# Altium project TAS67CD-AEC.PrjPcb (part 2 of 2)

## Sheet PROC191_TAS1.SchDoc
size 431 x 279 mm; Date: Not shown in title block; ApprovedBy: Not shown in title block; CheckedBy: Not shown in title block; Author: Not shown in title block; CompanyName: Not shown in title block; Engineer: Not shown in title block; Organization: Not shown in title block; Address1: Not shown in title block; Address2: Not shown in title block; Address3: Not shown in title block; Address4: Not shown in title block; DocumentNumber: 4; Revision: Use project parameter SCH_Rev; SheetNumber: 5; SheetTotal: 6; PageSetup: Record=PageOptions¦CenterHorizontal=True¦CenterVertical=True¦PrintScale=1.00¦XCorrection=1.00¦YCorrection=1.00¦PrintKind=0¦BorderSize=5000000¦LeftOffset=0¦BottomOffset=0¦Orientation=2¦PaperLength=1000¦PaperWidth=1000¦Scale=100¦PaperSource=15¦PrintQuality=600¦MediaType=1¦DitherType=10¦PaperKind=Letter¦PrintScaleMode=1
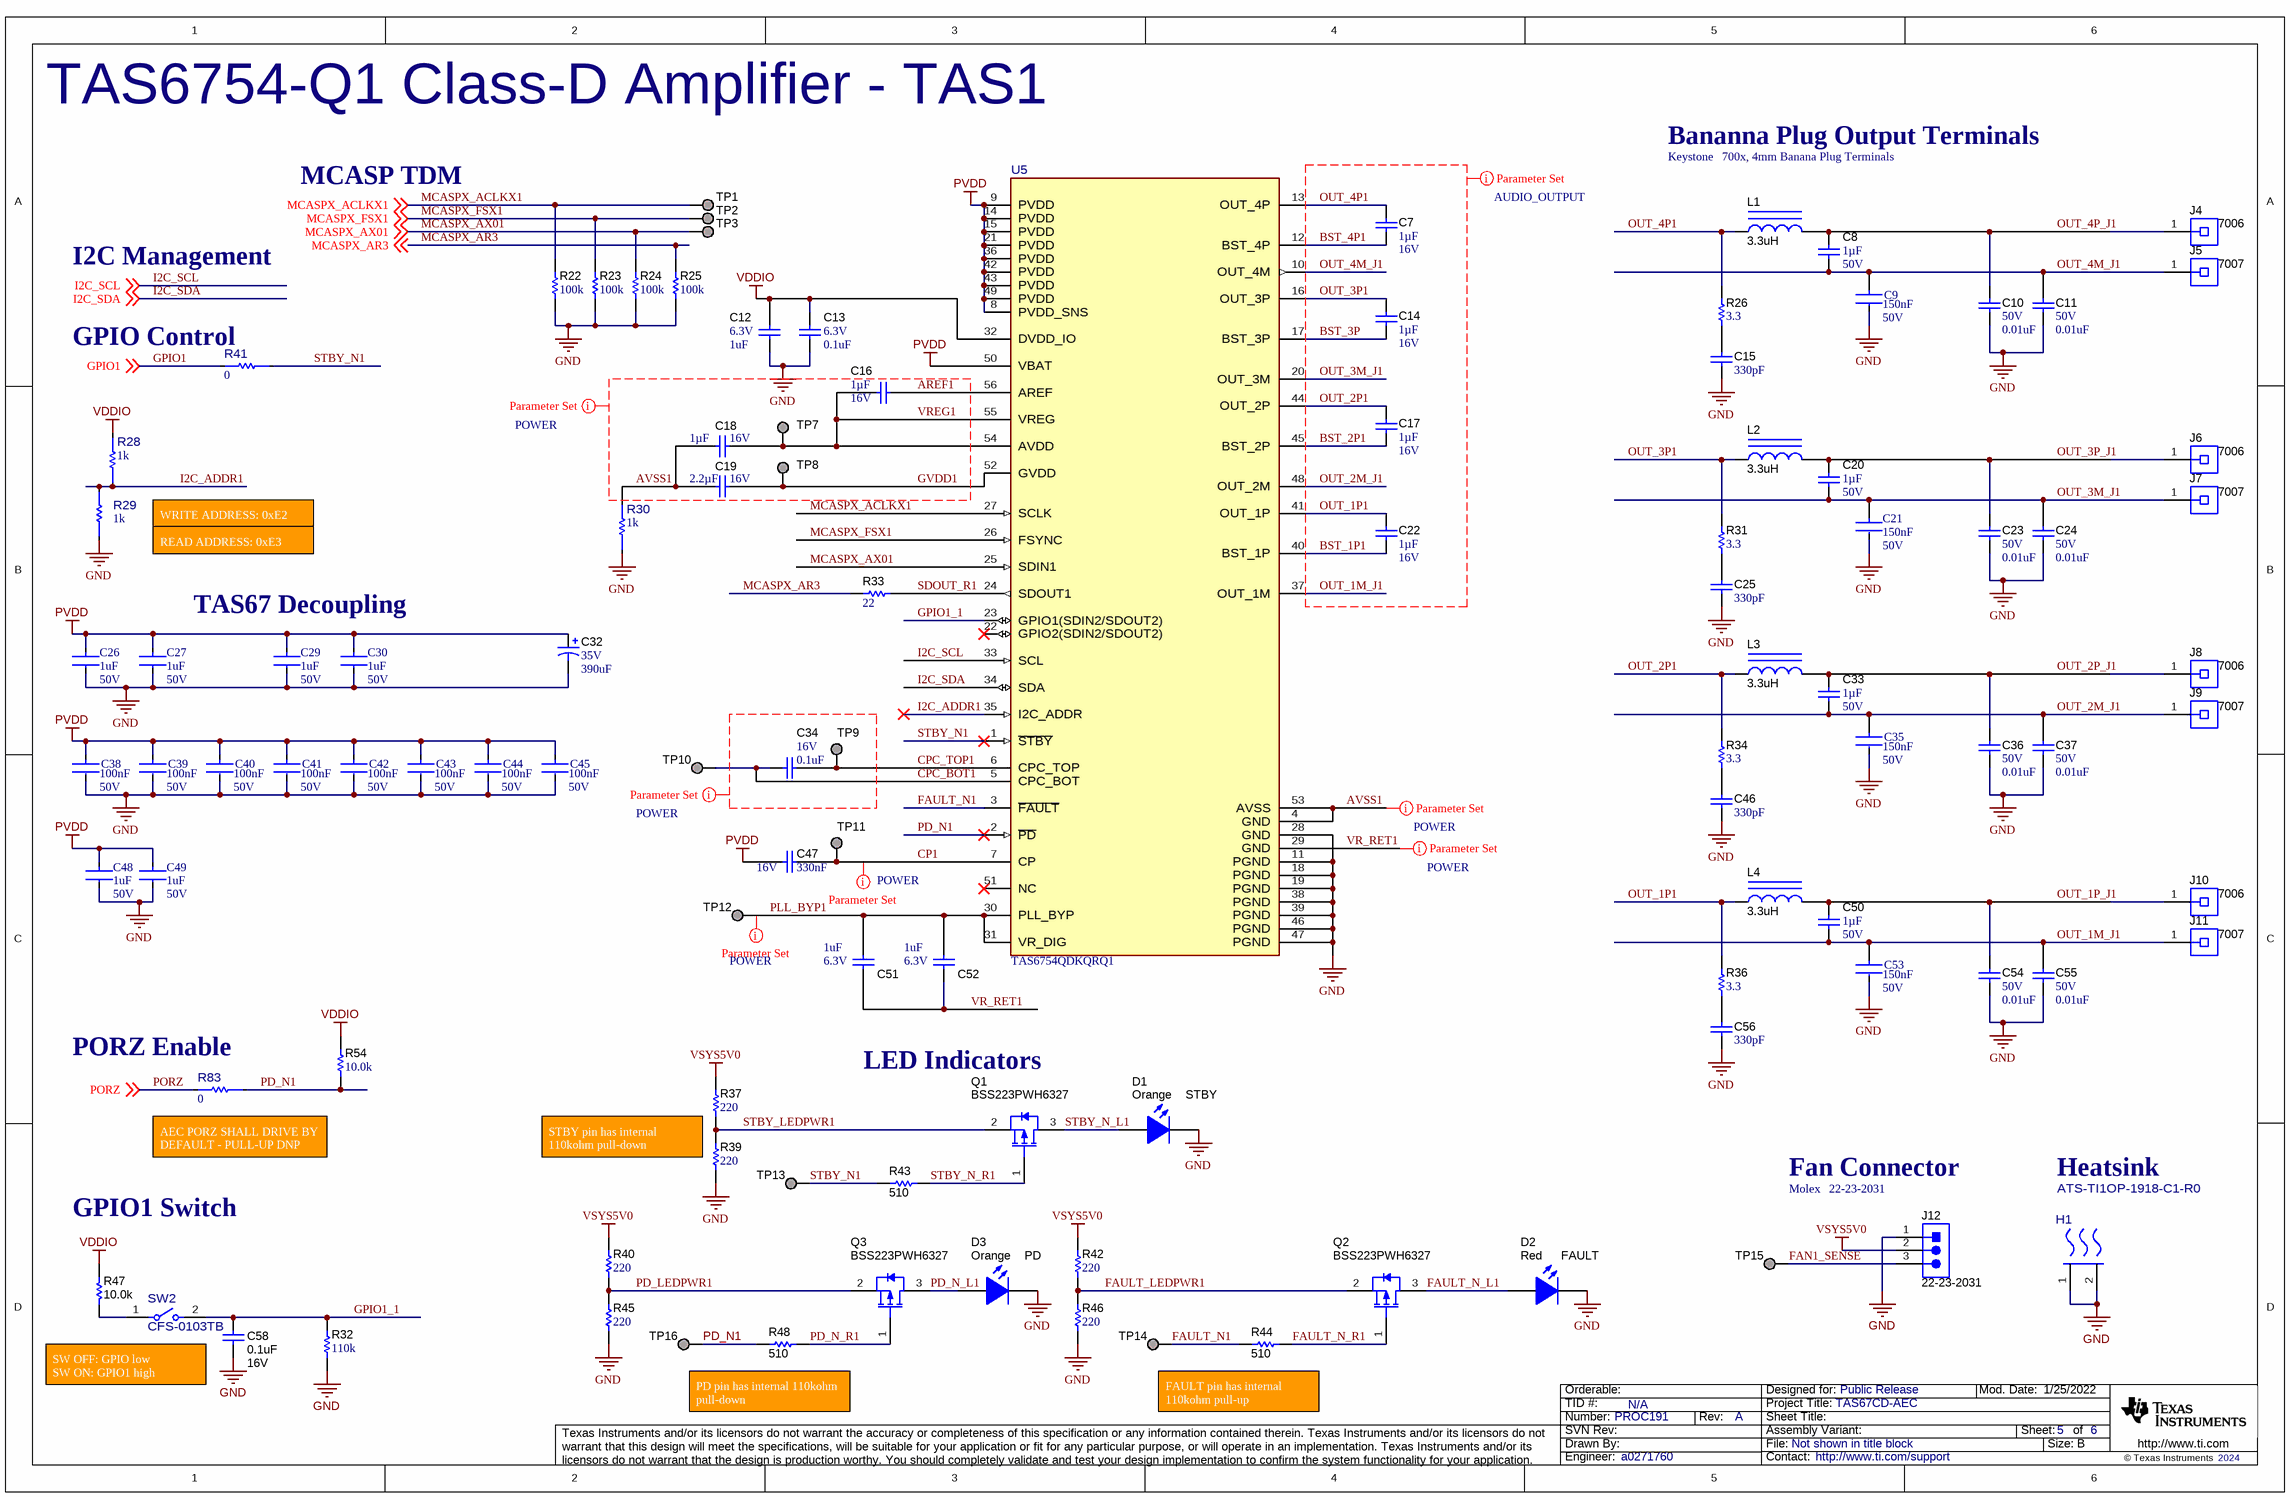
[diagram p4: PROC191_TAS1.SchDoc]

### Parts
C7  Cap_F: 1µF  VDC_V: 16V  [0603]  (hidden comment: GCM188R71C105KA64D)
C8  Cap_F: 1µF  VDC_V: 50V  [0805_HV]  (hidden comment: GCM21BR71H105KA03K)
C9  Voltage Rating: 50V  Capacitance: 150nF  [FP-GCM188-0_1-IPC_C]  (hidden comment: GCM188R71H154KA64D)
C10  VDC_V: 50V  ValueDisplayed: 0.01uF  [0603]  (hidden comment: GRM1885C1H103JA01D)
C11  VDC_V: 50V  ValueDisplayed: 0.01uF  [0603]  (hidden comment: GRM1885C1H103JA01D)
C12  VDC_V: 6.3V  ValueDisplayed: 1uF  [0402]  (hidden comment: GRM155R70J105KA12D)
C13  VDC_V: 6.3V  ValueDisplayed: 0.1uF  [0402]  (hidden comment: GRM155R70J104KA01D)
C14  Cap_F: 1µF  VDC_V: 16V  [0603]  (hidden comment: GCM188R71C105KA64D)
C15  ValueDisplayed: 330pF  [0402]  (hidden comment: GRM155R71H331KA01D)
C16  Cap_F: 1µF  VDC_V: 16V  [0603]  (hidden comment: GCM188R71C105MA64D)
C17  Cap_F: 1µF  VDC_V: 16V  [0603]  (hidden comment: GCM188R71C105KA64D)
C18  Cap_F: 1µF  VDC_V: 16V  [0603]  (hidden comment: GCM188R71C105MA64D)
C19  Cap_F: 2.2µF  VDC_V: 16V  [0603]  (hidden comment: EMK107BB7225KA-T)
C20  Cap_F: 1µF  VDC_V: 50V  [0805_HV]  (hidden comment: GCM21BR71H105KA03K)
C21  Voltage Rating: 50V  Capacitance: 150nF  [FP-GCM188-0_1-IPC_C]  (hidden comment: GCM188R71H154KA64D)
C22  Cap_F: 1µF  VDC_V: 16V  [0603]  (hidden comment: GCM188R71C105KA64D)
C23  VDC_V: 50V  ValueDisplayed: 0.01uF  [0603]  (hidden comment: GRM1885C1H103JA01D)
C24  VDC_V: 50V  ValueDisplayed: 0.01uF  [0603]  (hidden comment: GRM1885C1H103JA01D)
C25  ValueDisplayed: 330pF  [0402]  (hidden comment: GRM155R71H331KA01D)
C26  Voltage Rating: 50V  Capacitance: 1uF  [FP-GCJ21B-0_3-IPC_A]  (hidden comment: GCJ21BR71H105MA01L)
C27  Voltage Rating: 50V  Capacitance: 1uF  [FP-GCJ21B-0_3-IPC_A]  (hidden comment: GCJ21BR71H105MA01L)
C29  Voltage Rating: 50V  Capacitance: 1uF  [FP-GCJ21B-0_3-IPC_A]  (hidden comment: GCJ21BR71H105MA01L)
C30  Voltage Rating: 50V  Capacitance: 1uF  [FP-GCJ21B-0_3-IPC_A]  (hidden comment: GCJ21BR71H105MA01L)
C32  VDC_V: 35V  ValueDisplayed: 390uF  [SM_RADIAL_10BMM]  (hidden comment: UCL1V391MNL1GS)
C33  Cap_F: 1µF  VDC_V: 50V  [0805_HV]  (hidden comment: GCM21BR71H105KA03K)
C34  VDC_V: 16V  ValueDisplayed: 0.1uF  [0402]  (hidden comment: GCM155R71C104KA55D)
C35  Voltage Rating: 50V  Capacitance: 150nF  [FP-GCM188-0_1-IPC_C]  (hidden comment: GCM188R71H154KA64D)
C36  VDC_V: 50V  ValueDisplayed: 0.01uF  [0603]  (hidden comment: GRM1885C1H103JA01D)
C37  VDC_V: 50V  ValueDisplayed: 0.01uF  [0603]  (hidden comment: GRM1885C1H103JA01D)
C38  Voltage Rating (DC): 50V  Capacitance: 100nF  [FP-GCJ188-0_2-IPC_C]  (hidden comment: GCJ188R71H104KA12D)
C39  Voltage Rating (DC): 50V  Capacitance: 100nF  [FP-GCJ188-0_2-IPC_C]  (hidden comment: GCJ188R71H104KA12D)
C40  Voltage Rating (DC): 50V  Capacitance: 100nF  [FP-GCJ188-0_2-IPC_C]  (hidden comment: GCJ188R71H104KA12D)
C41  Voltage Rating (DC): 50V  Capacitance: 100nF  [FP-GCJ188-0_2-IPC_C]  (hidden comment: GCJ188R71H104KA12D)
C42  Voltage Rating (DC): 50V  Capacitance: 100nF  [FP-GCJ188-0_2-IPC_C]  (hidden comment: GCJ188R71H104KA12D)
C43  Voltage Rating (DC): 50V  Capacitance: 100nF  [FP-GCJ188-0_2-IPC_C]  (hidden comment: GCJ188R71H104KA12D)
C44  Voltage Rating (DC): 50V  Capacitance: 100nF  [FP-GCJ188-0_2-IPC_C]  (hidden comment: GCJ188R71H104KA12D)
C45  Voltage Rating (DC): 50V  Capacitance: 100nF  [FP-GCJ188-0_2-IPC_C]  (hidden comment: GCJ188R71H104KA12D)
C46  ValueDisplayed: 330pF  [0402]  (hidden comment: GRM155R71H331KA01D)
C47  Cap_F: 330nF  VDC_V: 16V  [0603]  (hidden comment: GRM188R71C334KA01D)
C48  Voltage Rating: 50V  Capacitance: 1uF  [FP-GCJ21B-0_3-IPC_A]  (hidden comment: GCJ21BR71H105MA01L)
C49  Voltage Rating: 50V  Capacitance: 1uF  [FP-GCJ21B-0_3-IPC_A]  (hidden comment: GCJ21BR71H105MA01L)
C50  Cap_F: 1µF  VDC_V: 50V  [0805_HV]  (hidden comment: GCM21BR71H105KA03K)
C51  VDC_V: 6.3V  ValueDisplayed: 1uF  [0402]  (hidden comment: GRM155R70J105KA12D)
C52  VDC_V: 6.3V  ValueDisplayed: 1uF  [0402]  (hidden comment: GRM155R70J105KA12D)
C53  Voltage Rating: 50V  Capacitance: 150nF  [FP-GCM188-0_1-IPC_C]  (hidden comment: GCM188R71H154KA64D)
C54  VDC_V: 50V  ValueDisplayed: 0.01uF  [0603]  (hidden comment: GRM1885C1H103JA01D)
C55  VDC_V: 50V  ValueDisplayed: 0.01uF  [0603]  (hidden comment: GRM1885C1H103JA01D)
C56  ValueDisplayed: 330pF  [0402]  (hidden comment: GRM155R71H331KA01D)
C58  VDC_V: 16V  ValueDisplayed: 0.1uF  [0402]  (hidden comment: C0402C104K4RACAUTO)
D1  STBY  value Orange  [LTST-C170KFKT_Orange]
D2  FAULT  value Red  [LED_LTST-C170_Red]
D3  PD  value Orange  [LTST-C170KFKT_Orange]
H1  ATS-TI1OP-1918-C1-R0  [FP-ATS-TI1OP-1918-C1-R0_HTSNK_41MM4_20MM0-MFG]
J4  7006  Manufacturer: Keystone  [Keystone_7006]
J5  7007  [Keystone_7007]
J6  7006  [Keystone_7006]
J7  7007  [Keystone_7007]
J8  7006  [Keystone_7006]
J9  7007  [Keystone_7007]
J10  7006  [Keystone_7006]
J11  7007  [Keystone_7007]
J12  22-23-2031  Manufacturer: Molex  [Molex_22-23-2031]
L1  ValueDisplayed: 3.3uH  [VCMT053T]  (hidden comment: VCMT053T-3R3MN5)
L2  ValueDisplayed: 3.3uH  [VCMT053T]  (hidden comment: VCMT053T-3R3MN5)
L3  ValueDisplayed: 3.3uH  [VCMT053T]  (hidden comment: VCMT053T-3R3MN5)
L4  ValueDisplayed: 3.3uH  [VCMT053T]  (hidden comment: VCMT053T-3R3MN5)
Q1  BSS223PWH6327  [SOT-323]
Q2  BSS223PWH6327  [SOT-323]
Q3  BSS223PWH6327  [SOT-323]
R22  ValueDisplayed: 100k  [0402]  (hidden comment: RMCF0402FT100K)
R23  ValueDisplayed: 100k  [0402]  (hidden comment: RMCF0402FT100K)
R24  ValueDisplayed: 100k  [0402]  (hidden comment: RMCF0402FT100K)
R25  ValueDisplayed: 100k  [0402]  (hidden comment: RMCF0402FT100K)
R26  ValueDisplayed: 3.3  [0603]  (hidden comment: CRCW06033R30JNEA)
R28  Res_ohm: 1k  [FP-ERJ-3GEYJ102V_0603-MFG]  (hidden comment: ERJ-3GEYJ102V)
R29  Res_ohm: 1k  [FP-ERJ-3GEYJ102V_0603-MFG]  (hidden comment: ERJ-3GEYJ102V)
R30  Res_ohm: 1k  [FP-ERJ-3GEYJ102V_0603-MFG]  (hidden comment: ERJ-3GEYJ102V)
R31  ValueDisplayed: 3.3  [0603]  (hidden comment: CRCW06033R30JNEA)
R32  ValueDisplayed: 110k  [0603]  (hidden comment: RC0603FR-07110KL)
R33  ValueDisplayed: 22  [0402]  (hidden comment: ERJ-2GEJ220X)
R34  ValueDisplayed: 3.3  [0603]  (hidden comment: CRCW06033R30JNEA)
R36  ValueDisplayed: 3.3  [0603]  (hidden comment: CRCW06033R30JNEA)
R37  ValueDisplayed: 220  [0402]  (hidden comment: ERJ-2RKF2200X)
R39  ValueDisplayed: 220  [0402]  (hidden comment: ERJ-2RKF2200X)
R40  ValueDisplayed: 220  [0402]  (hidden comment: ERJ-2RKF2200X)
R41  Res_ohm: 0  [FP-ERJ-3GEY0R00V_0603-IPC_B]  (hidden comment: ERJ-3GEY0R00V)
R42  ValueDisplayed: 220  [0402]  (hidden comment: ERJ-2RKF2200X)
R43  ValueDisplayed: 510  [0402]  (hidden comment: ERJ-2GEJ511X)
R44  ValueDisplayed: 510  [0402]  (hidden comment: ERJ-2GEJ511X)
R45  ValueDisplayed: 220  [0402]  (hidden comment: ERJ-2RKF2200X)
R46  ValueDisplayed: 220  [0402]  (hidden comment: ERJ-2RKF2200X)
R47  ValueDisplayed: 10.0k  [0402]  (hidden comment: RMCF0402FT10K0)
R48  ValueDisplayed: 510  [0402]  (hidden comment: ERJ-2GEJ511X)
R54  ValueDisplayed: 10.0k  [0603]  (hidden comment: RC0603FR-0710KL)
R83  Res_ohm: 0  [FP-ERJ-3GEY0R00V_0603-IPC_B]  (hidden comment: ERJ-3GEY0R00V)
SW2  CFS-0103TB  [FP-CFS-0103TB_SMT_SW_6MM40_3MM95-MFG]
TP1  AVDD  [TP_SM_1MM]  (value not drawn)  (no BOM)
TP2  AVDD  [TP_SM_1MM]  (value not drawn)  (no BOM)
TP3  AVDD  [TP_SM_1MM]  (value not drawn)  (no BOM)
TP7  AVDD  [TP_SM_1MM]  (value not drawn)  (no BOM)
TP8  AVDD  [TP_SM_1MM]  (value not drawn)  (no BOM)
TP9  CPC_TOP  [TP_SM_1MM]  (value not drawn)  (no BOM)
TP10  CPC_BOT  [TP_SM_1MM]  (value not drawn)  (no BOM)
TP11  CP  [TP_SM_1MM]  (value not drawn)  (no BOM)
TP12  VR_DIG  [TP_SM_1MM]  (value not drawn)  (no BOM)
TP13  FAULT  [TP_SM_1MM]  (value not drawn)  (no BOM)
TP14  FAULT  [TP_SM_1MM]  (value not drawn)  (no BOM)
TP15  VR_DIG  [TP_SM_1MM]  (value not drawn)  (no BOM)
TP16  FAULT  [TP_SM_1MM]  (value not drawn)  (no BOM)
U5  TAS6754QDKQRQ1  [DKQ0056C-MFG]

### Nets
GND: C9.2 C10.2 C11.2 C12.2 C13.2 C15.1 C21.2 C23.2 C24.2 C25.1 C26.2 C27.2 C29.2 C30.2 C32.2(-) C35.2 C36.2 C37.2 C38.1 C39.1 C40.1 C41.1 C42.1 C43.1 C44.1 C45.1 C46.1 C48.2 C49.2 C53.2 C54.2 C55.2 C56.1 C58.2 D1.2(K) D2.2(K) D3.2(K) H1.1(MNT_1) H1.2(MNT_2) J12.1 R22.1 R23.1 R24.1 R25.1 R29.1 R30.1 R32.1 R39.2 R45.2 R46.2 U5.11(PGND) U5.18(PGND) U5.19(PGND) U5.28(GND) U5.38(PGND) U5.39(PGND) U5.46(PGND) U5.47(PGND)
PVDD: C26.1 C27.1 C29.1 C30.1 C32.1(+) C38.2 C39.2 C40.2 C41.2 C42.2 C43.2 C44.2 C45.2 C47.2 C48.1 C49.1 U5.8(PVDD_SNS) U5.9(PVDD) U5.14(PVDD) U5.15(PVDD) U5.21(PVDD) U5.36(PVDD) U5.42(PVDD) U5.43(PVDD) U5.49(PVDD) U5.50(VBAT)
VDDIO: C12.1 C13.1 R28.2 R47.2 R54.2 U5.32(DVDD_IO)
VSYS5V0: J12.2 R37.1 R40.1 R42.1
AREF1: C16.1 U5.56(AREF)
AVSS1: C18.2 C19.1 R30.2 U5.4(GND) U5.53(AVSS)
BST_1P1: C22.1 U5.40(BST_1P)
BST_2P1: C17.1 U5.45(BST_2P)
BST_3P: C14.1 U5.17(BST_3P)
BST_4P1: C7.1 U5.12(BST_4P)
CP1: C47.1 TP11.1 U5.7(CP)
CPC_BOT1: C34.1 TP10.1 U5.5(CPC_BOT)
CPC_TOP1: C34.2 TP9.1 U5.6(CPC_TOP)
FAN1_SENSE: J12.3 TP15.1
FAULT_LEDPWR1: Q2.2(S) R42.2 R46.1
FAULT_N1: R44.2 TP14.1 U5.3(~{FAULT})
FAULT_N_L1: D2.1(A) Q2.3(D)
FAULT_N_R1: Q2.1(G) R44.1
GPIO1: R41.2 ; off-sheet GPIO1
GPIO1_1: C58.1 R32.2 SW2.2 U5.23(GPIO1(SDIN2/SDOUT2))
GVDD1: C19.2 TP8.1 U5.52(GVDD)
I2C_ADDR1: R28.1 R29.2 U5.35(I2C_ADDR)
I2C_SCL: U5.33(SCL) ; off-sheet I2C_SCL
I2C_SDA: U5.34(SDA) ; off-sheet I2C_SDA
MCASPX_ACLKX1: R22.2 TP1.1 U5.27(SCLK) ; off-sheet MCASPX_ACLKX1
MCASPX_AR3: R25.2 R33.1 ; off-sheet MCASPX_AR3
MCASPX_AX01: R24.2 TP3.1 U5.25(SDIN1) ; off-sheet MCASPX_AX01
MCASPX_FSX1: R23.2 TP2.1 U5.26(FSYNC) ; off-sheet MCASPX_FSX1
OUT_1M_J1: C50.2 C53.1 C55.1 J11.1 U5.37(OUT_1M)
OUT_1P1: C22.2 L4.1 R36.2 U5.41(OUT_1P)
OUT_1P_J1: C50.1 C54.1 J10.1 L4.2
OUT_2M_J1: C33.2 C35.1 C37.1 J9.1 U5.48(OUT_2M)
OUT_2P1: C17.2 L3.1 R34.2 U5.44(OUT_2P)
OUT_2P_J1: C33.1 C36.1 J8.1 L3.2
OUT_3M_J1: C20.2 C21.1 C24.1 J7.1 U5.20(OUT_3M)
OUT_3P1: C14.2 L2.1 R31.2 U5.16(OUT_3P)
OUT_3P_J1: C20.1 C23.1 J6.1 L2.2
OUT_4M_J1: C8.2 C9.1 C11.1 J5.1 U5.10(OUT_4M)
OUT_4P1: C7.2 L1.1 R26.2 U5.13(OUT_4P)
OUT_4P_J1: C8.1 C10.1 J4.1 L1.2
PD_LEDPWR1: Q3.2(S) R40.2 R45.1
PD_N1: R48.2 R54.1 R83.1 TP16.1 U5.2(~{PD})
PD_N_L1: D3.1(A) Q3.3(D)
PD_N_R1: Q3.1(G) R48.1
PLL_BYP1: C51.1 C52.1 TP12.1 U5.30(PLL_BYP) U5.31(VR_DIG)
PORZ: R83.2 ; off-sheet PORZ
SDOUT_R1: R33.2 U5.24(SDOUT1)
STBY_LEDPWR1: Q1.2(S) R37.2 R39.1
STBY_N1: R41.1 R43.2 TP13.1 U5.1(~{STBY})
STBY_N_L1: D1.1(A) Q1.3(D)
STBY_N_R1: Q1.1(G) R43.1
VR_RET1: C51.2 C52.2 U5.29(GND)
VREG1: C16.2 C18.1 TP7.1 U5.54(AVDD) U5.55(VREG)
NetC15_2: C15.2 R26.1
NetC25_2: C25.2 R31.1
NetC46_2: C46.2 R34.1
NetC56_2: C56.2 R36.1
NetR47_1: R47.1 SW2.1

Not connected (* = marked no-connect by the designer): U5 22(GPIO2(SDIN2/SDOUT2))* 51(NC)*

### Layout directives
net class AUDIO_OUTPUT: BST_1P1, BST_2P1, BST_3P, BST_4P1, OUT_1M_J1, OUT_1P1, OUT_2M_J1, OUT_2P1, OUT_3M_J1, OUT_3P1, OUT_4M_J1, OUT_4P1
net class POWER: (no net found under the mark), AREF1, AVSS1, CP1, GVDD1, PLL_BYP1, VR_RET1, VREG1

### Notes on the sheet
- TAS6754-Q1 Class-D Amplifier - TAS1
- Bananna Plug Output Terminals
- 700x, 4mm Banana Plug Terminals
- MCASP TDM
- I2C Management
- (near R41) GPIO Control
- WRITE ADDRESS: 0xE2
- READ ADDRESS: 0xE3
- TAS67 Decoupling
- (near R83) PORZ Enable
- LED Indicators
- AEC PORZ SHALL DRIVE BY DEFAULT - PULL-UP DNP
- STBY pin has internal 110kohm pull-down
- Fan Connector
- Heatsink
- GPIO1 Switch
- SW OFF: GPIO low
  SW ON: GPIO1 high
- PD pin has internal 110kohm pull-down
- FAULT pin has internal 110kohm pull-up

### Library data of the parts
C7 C14 C17 C22 = CMP-0007136-5: CAP, CERM, 1 uF, 16 V, +/- 10%, X7R, AEC-Q200 Grade 1, 0603; Manufacturer: MuRata; TaMin_C: -55°C; Polarized: N; SizeAreaWB_mm2: 4.68; Value1: Unknown; U/M: EA; Value: 1uF; TaMax_C: 125°C; SizeZ_mm: 1; SizeX_mm: 1.6; SizeY_mm: 0.8; SizeArea_mm2: 1.28; AEC Qualified: Y; AEC Category: Q200
C8 C20 C33 C50 = CMP-0086249-1: CAP, CERM, 1 µF, 50 V,+/- 10%, X7R, AEC-Q200 Grade 1, 0805; Manufacturer: MuRata; Value: 1uF; AEC Qualified: Y; AEC Category: Q200; U/M: EA; AEC Grade: 1; SizeArea_mm2: 2.5; SizeAreaWB_mm2: 6.75; SizeZ_mm: 1.45; SizeX_mm: 2; Cap_Case: 0805; TaMax_C: 125°C; Polarized: N; SizeY_mm: 1.25; TaMin_C: -55°C
C9 C21 C35 C53 = CMP-2006-02379-2: Ceramic Capacitor for Automotive 150nF  ±10% 50VDC X7R 0603 Paper T/R
C10 C11 C23 C24 C36 C37 C54 C55 = CMP-0007174-4: CAP, CERM, 0.01 uF, 50 V, +/- 5%, C0G/NP0, 0603; Manufacturer: MuRata; TaMin_C: -55°C; Polarized: N; SizeAreaWB_mm2: 4.68; Value1: Unknown; U/M: EA; Value: 0.01uF; TaMax_C: 125°C; SizeZ_mm: 1; SizeX_mm: 1.6; SizeY_mm: 0.8; SizeArea_mm2: 1.28; Cap_F: 10nF; AEC Category: Q200
C12 C51 C52 = CMP-0064947-2: CAP, CERM, 1 uF, 6.3 V,+/- 10%, X7R, 0402; Manufacturer: MuRata; TaMin_C: -55°C; Polarized: N; SizeAreaWB_mm2: 3; Value1: Unknown; U/M: EA; Value: 1uF; TaMax_C: 125°C; SizeZ_mm: 0.6; SizeX_mm: 1; SizeY_mm: 0.5; Cap_F: 1µF; AEC Category: Q200
C13 = CMP-0006623-2: CAP, CERM, 0.1 uF, 6.3 V, +/- 10%, X7R, 0402; Manufacturer: MuRata; TaMin_C: -55°C; Polarized: N; SizeAreaWB_mm2: 3; Value1: Unknown; U/M: EA; Value: 0.1uF; TaMax_C: 125°C; SizeZ_mm: 0.6; SizeX_mm: 1; SizeY_mm: 0.5; Cap_F: 100nF; AEC Category: Q200
C15 C25 C46 C56 = CMP-0006687-2: CAP, CERM, 330 pF, 50 V, +/- 10%, X7R, 0402; Manufacturer: MuRata; TaMin_C: -55°C; Polarized: N; SizeAreaWB_mm2: 3; Value1: Unknown; U/M: EA; Value: 330pF; TaMax_C: 125°C; SizeZ_mm: 0.6; SizeX_mm: 1; SizeY_mm: 0.5; Value2: 50V; AEC Category: Q200
C16 C18 = CMP-0007137-5: CAP, CERM, 1 uF, 16 V, +/- 20%, X7R, AEC-Q200 Grade 1, 0603; Manufacturer: MuRata; TaMin_C: -55°C; Polarized: N; SizeAreaWB_mm2: 4.68; Value1: Unknown; U/M: EA; Value: 1uF; TaMax_C: 125°C; SizeZ_mm: 1; SizeX_mm: 1.6; SizeY_mm: 0.8; SizeArea_mm2: 1.28; AEC Qualified: Y; AEC Category: Q200
C19 = CMP-0007121-4: CAP, CERM, 2.2 uF, 16 V, +/- 10%, X7R, 0603; Manufacturer: Taiyo Yuden; TaMin_C: -55°C; Polarized: N; SizeAreaWB_mm2: 4.68; Value1: Unknown; U/M: EA; Value: 2.2uF; TaMax_C: 125°C; SizeZ_mm: 1; SizeX_mm: 1.6; SizeY_mm: 0.8; SizeArea_mm2: 1.28; AEC Category: Q200
C26 C27 C29 C30 C48 C49 = CMP-06035-059042-1: Multilayer Ceramic Capacitors MLCC - SMD/SMT 0805 1uF 20%, 50VDC,  X7R 15%
C32 = CMP-0011092-1: CAP, AL, 390 uF, 35 V, +/- 20%, 0.08 ohm, SMD; Manufacturer: Nichicon; TaMin_C: -55°C; ESR_ohm: 80m; Polarized: Y; SizeAreaWB_mm2: 159.9; U/M: EA; Value: 390uF; TaMax_C: 105°C; SizeZ_mm: 10.2; SizeX_mm: 11; SizeY_mm: 10.3; Cap_Case: 10x10; SizeArea_mm2: 113.3; CompType: Capacitor; Cap_F: 390µF; IRMS_A: 850mA; AEC Category: Q200
C34 = CMP-0006351-2: CAP, CERM, 0.1 uF, 16 V, +/- 10%, X7R, 0402; Manufacturer: MuRata; TaMin_C: -55°C; Polarized: N; SizeAreaWB_mm2: 3; Value1: Unknown; U/M: EA; Value: 0.1uF; TaMax_C: 125°C; SizeZ_mm: 0.6; SizeX_mm: 1; SizeY_mm: 0.5; Cap_F: 100nF; AEC Category: Q200
C38-C45 = CMP-2006-02223-2: Cap Ceramic 0.1uF 50V X7R 10% Pad SMD 0603 Soft Termination +125°C Automotive T/R
C47 = CMP-0007393-4: CAP, CERM, 0.33 uF, 16 V, +/- 10%, X7R, 0603; Manufacturer: MuRata; TaMin_C: -55°C; Polarized: N; SizeAreaWB_mm2: 4.68; Value1: Unknown; U/M: EA; Value: 0.33uF; TaMax_C: 125°C; SizeZ_mm: 1; SizeX_mm: 1.6; SizeY_mm: 0.8; SizeArea_mm2: 1.28; AEC Category: Q200
C58 = CMP-0006237-2: CAP, CERM, 0.1 uF, 16 V, +/- 10%, X7R, AEC-Q200 Grade 1, 0402; Manufacturer: Kemet; TaMin_C: -55°C; Polarized: N; SizeAreaWB_mm2: 3; Value1: Unknown; U/M: EA; Value: 0.1uF; TaMax_C: 125°C; SizeZ_mm: 0.6; SizeX_mm: 1; SizeY_mm: 0.5; AEC Qualified: Y; Cap_F: 100nF; AEC Category: Q200
D1 D3 = CMP-0002890-1: LED, Orange, SMD; Manufacturer: Lite-On; PartNumber: LTST-C170KFKT; Io_A: 20mA; Value1: W; U/M: EA; Vf_V: 2V; Type: AlInGaP
D2 = CMP-0002829-3: LED, Red, SMD; Manufacturer: Lite-On; PartNumber: LTST-C170KRKT; SizeZ_mm: 1.2; Value1: W; SizeY_mm: 1.25; Value2: 2V; SizeArea_mm2: 2.5; SizeX_mm: 2; SizeAreaWB_mm2: 6.75; Io_A: 20mA; Type: AlInGaP
H1 = CMP-0123147-2: 20.0 x 41.4 x 32.8 mm  BGA Heat Sink - High Performance Device Specific - TI; Manufacturer: Advanced Thermal Solutions; AEC Qualified: No; SizeZ_mm: 32.77mm; Thermal Resistance Forced Air Flow: 4.6°C/W
J4 = CMP-0055127-1: Binding Post, RED, TH; CNHeader: FALSE; Green_Lifecycle: Active; Green_REACh: Passed; CompType: Connector
J5 J7 J9 J11 = CMP-0055128-1: Binding Post, BLACK, TH; Manufacturer: Keystone; CNHeader: FALSE; Green_Lifecycle: Active; Green_REACh: Passed; CompType: Connector
J6 J8 J10 = CMP-0055127-1: Binding Post, RED, TH; Manufacturer: Keystone; CNHeader: FALSE; Green_Lifecycle: Active; Green_REACh: Passed; CompType: Connector
J12 = CMP-0055322-1: Header, 2.54 mm, 3x1, Tin, TH; CNHeader: TRUE; Green_Lifecycle: Active; Shrouded: N; Gender: Male; Green_REACh: Passed; Row_Count: 1; Pitch_mm: 2.54; CT: FALSE
L1-L4 = CMP-0059924-1: Inductor, 3.3 uH, 4.5 A, 0.038 ohm, AEC-Q200 Grade 0, SMD; Manufacturer: Cyntec; Isat: 4.5A @ 30% inductance drop; Irms: 5A @ 40C rise; SizeAreaWB_mm2: 54.0125; DCR_ohm: 0.038; Value: 3.3uH; Imax_A: 4.5A; SizeZ_mm: 3; SizeX_mm: 5.45; SizeY_mm: 5.25; SizeArea_mm2: 28.6125; Ind_H: 3.3µH; AEC Qualified: Y; AEC Grade: 0; AEC Category: Q200
Q1-Q3 = CMP-0000010-3: MOSFET, P-CH, -20 V, -0.39 A, SOT-323; Alternate Manufacturer: None; Manufacturer: Infineon Technologies; Value: -20V; Rdson45_ohm: 1.2; SizeX_mm: 2.2; AEC Category: Q101; ChMode: Enhancement; Vgs_V: -12V; Value1: 1; IdsMax_A: -390mA; ChType: P; SizeAreaWB_mm2: 10.24; QgTyp_nC: -0.5; SizeArea_mm2: 4.84; SizeZ_mm: 1.1
R22-R25 = CMP-0026753-1: RES, 100 k, 1%, 0.063 W, AEC-Q200 Grade 0, 0402; Manufacturer: Stackpole Electronics Inc; Power_W: 63mW; TempCo: 100 ppm/C; U/M: EA; Value: 100k; EIA_Code: E96; SizeX_mm: 1; SizeY_mm: 0.5; SizeZ_mm: 0.6; Value2: 0.063W; AEC Qualified: Y; VDC_V: 50V; AEC Grade: 0; AEC Category: Q200
R26 R31 R34 R36 = CMP-0025805-4: RES, 3.3, 5%, 0.1 W, AEC-Q200 Grade 0, 0603; Manufacturer: Vishay-Dale; Power_W: 100mW; TempCo: 200 ppm/C; Value_Code: 3R30; Value: 3.3; EIA_Code: E24; SizeX_mm: 1.6; SizeY_mm: 0.8; SizeZ_mm: 1; Value2: 0.1W; SizeArea_mm2: 1.28; AEC Qualified: Y; VDC_V: 75V; AEC Category: Q200; AEC Grade: 0
R28-R30 = CMP-0089144-1: 1 kOhms ±5% 0.1W, 1/10W Chip Resistor 0603 (1608 Metric) Automotive AEC-Q200 Thick Film; Manufacturer: Panasonic; Power_W: 100mW; AEC Qualified: Yes; Voltage: 75V; AEC Grade: Grade 0; SizeZ_mm: 0.55mm; TempCo: 200ppm/°C
R32 = CMP-0022752-4: RES, 110 k, 1%, 0.1 W, 0603; Manufacturer: Yageo; Power_W: 100mW; TempCo: 100 ppm/C; Value: 110k; EIA_Code: E96; SizeX_mm: 1.6; SizeY_mm: 0.8; SizeZ_mm: 1; Value2: 0.1W; SizeArea_mm2: 1.28; AEC Qualified: N; VDC_V: 75V; AEC Category: Q200; SizeAreaWB_mm2: 4.68
R33 = CMP-0026997-2: RES, 22, 5%, 0.1 W, AEC-Q200 Grade 0, 0402; Manufacturer: Panasonic; Power_W: 100mW; TempCo: 200 ppm/C; Value_Code: 22R0; U/M: EA; Value: 22; EIA_Code: E24; SizeX_mm: 1; SizeY_mm: 0.5; SizeZ_mm: 0.6; Value2: 0.1W; AEC Qualified: Y; AEC Grade: 0; AEC Category: Q200
R37 R39 R40 R42 R45 R46 = CMP-0026680-1: RES, 220, 1%, 0.1 W, AEC-Q200 Grade 0, 0402; Manufacturer: Panasonic; Power_W: 100mW; TempCo: 100 ppm/C; Value_Code: 220R; U/M: EA; Value: 220; SizeX_mm: 1; SizeY_mm: 0.5; SizeZ_mm: 0.6; Value2: 0.1W; AEC Qualified: Y; VDC_V: 50V; AEC Grade: 0; AEC Category: Q200
R41 R83 = CMP-0089143-1: 0 Ohms Jumper 0.1W, 1/10W Chip Resistor 0603 (1608 Metric) Automotive AEC-Q200 Thick Film; Manufacturer: Panasonic; SizeZ_mm: 0.55mm; AEC Grade: Grade 0; VDC_V: 75V; TempCo: -100/+600ppm/°C; AEC Qualified: Yes; Power_W: 100mW; Tolerance_%: 5%
R43 R44 R48 = CMP-0078212-1: RES, 510, 5%, 0.1 W, AEC-Q200 Grade 0, 0402; Manufacturer: Panasonic; Value_Code: 510R; SizeArea_mm2: 0.5; AEC Qualified: Y; AEC Category: Q200; Value: 510; SizeZ_mm: 0.6; EIA_Code: E24; TempCo: 200 ppm/C; AEC Grade: 0; Power_W: 100mW; VDC_V: 50V; Value2: 0.1W; U/M: EA; SizeX_mm: 1
R47 = CMP-0026754-1: RES, 10.0 k, 1%, 0.063 W, AEC-Q200 Grade 0, 0402; Manufacturer: Stackpole Electronics Inc; Power_W: 63mW; TempCo: 100 ppm/C; Value_Code: 10k0; U/M: EA; Value: 10.0k; EIA_Code: E96; Res_ohm: 10k; SizeX_mm: 1; SizeY_mm: 0.5; SizeZ_mm: 0.6; Value2: 0.063W; CompType: Resistor; AEC Qualified: Y; VDC_V: 50V; AEC Grade: 0; AEC Category: Q200
R54 = CMP-0022746-5: RES, 10.0 k, 1%, 0.1 W, 0603; Manufacturer: Yageo; Power_W: 100mW; TempCo: 100 ppm/C; Value_Code: 10k0; Value: 10.0k; EIA_Code: E96; Res_ohm: 10k; SizeX_mm: 1.6; SizeY_mm: 0.8; SizeZ_mm: 1; Value2: 0.1W; SizeArea_mm2: 1.28; AEC Qualified: N; VDC_V: 75V; AEC Category: Q200; SizeAreaWB_mm2: 4.68
SW2 = CMP-0120665-1: DIP Switch, 1 POS, SPST, Raised, 6VDC, 100mA, CFS Series; Manufacturer: Nidec Components Corporation; PositionCount: 1; SizeZ_mm: 5.3mm; VDC_V: 6V; AEC Qualified: No; Coil Resistance_ohm: 50mΩ; Electromechanical Life: 1000Cycles; Standoff Height: 0.1mm
TP1-TP3 TP7-TP16 = CMP-0003825-1: 1mm Test Point, SMT; Manufacturer: Any
U5 = CMP-0096441-1: 26.4 V, 7.5 A Digital Input 4-Channel Automotive Class-D Audio Amplifier with Current Sense and Real-time Load Diagnostics; Manufacturer: Texas Instruments; Part Number: TAS6554QDKQRQ1; Power At Speaker R: 50W @ 2Ω; Max Supply Voltage: 26.4V; TaMax_C: +125°C; SizeZ_mm: 2.475mm; Min Supply Voltage: 4.5V; AEC Qualified: Yes; AEC Grade: Grade 1; TaMin_C: -40°C; Standoff Height: 0mm; Number Of Channels: 4

## Sheet PROC191_Hardware.SchDoc
size 431 x 279 mm; Date: Not shown in title block; ApprovedBy: Not shown in title block; CheckedBy: Not shown in title block; Author: Not shown in title block; CompanyName: Not shown in title block; Engineer: Not shown in title block; Organization: Not shown in title block; Address1: Not shown in title block; Address2: Not shown in title block; Address3: Not shown in title block; Address4: Not shown in title block; DocumentNumber: 5; Revision: Use project parameter SCH_Rev; SheetNumber: 6; SheetTotal: 6; PageSetup: Record=PageOptions¦CenterHorizontal=True¦CenterVertical=True¦PrintScale=1.00¦XCorrection=1.00¦YCorrection=1.00¦PrintKind=0¦BorderSize=5000000¦LeftOffset=0¦BottomOffset=0¦Orientation=2¦PaperLength=1000¦PaperWidth=1000¦Scale=100¦PaperSource=15¦PrintQuality=600¦MediaType=1¦DitherType=10¦PaperKind=Letter¦PrintScaleMode=1
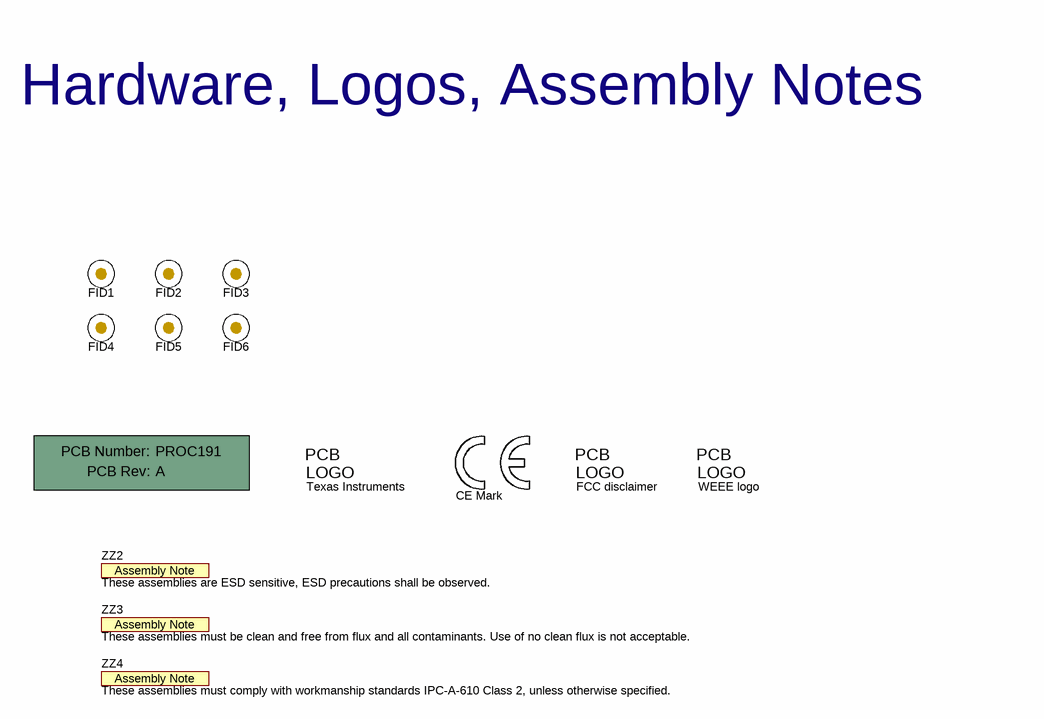
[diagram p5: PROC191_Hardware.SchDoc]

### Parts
!PCB1  Printed Circuit Board  (value not drawn)  (mechanical)
FID1  Fiducial  [Fiducial10-20]  (value not drawn)  (no BOM)
FID2  Fiducial  [Fiducial10-20]  (value not drawn)  (no BOM)
FID3  Fiducial  [Fiducial10-20]  (value not drawn)  (no BOM)
FID4  Fiducial  [Fiducial10-20]  (value not drawn)  (no BOM)
FID5  Fiducial  [Fiducial10-20]  (value not drawn)  (no BOM)
FID6  Fiducial  [Fiducial10-20]  (value not drawn)  (no BOM)
Logo1  CE Mark  [CE_Mark_5mm]  (no BOM)
Logo2  Texas Instruments  [TI_Symbol_Overlay_Small]  (no BOM)
Logo3  FCC disclaimer  [FCC_disclaimer]  (no BOM)
Logo4  WEEE logo  [WEEE_Minimum]  (no BOM)
ZZ2  These assemblies are ESD sensitive, ESD precautions shall be observed.  [AssemblyNote]  (no BOM)
ZZ3  These assemblies must be clean and free from flux and all contaminants. Use of no clean flux is not acceptable.  [AssemblyNote]  (no BOM)
ZZ4  These assemblies must comply with workmanship standards IPC-A-610 Class 2, unless otherwise specified.  [AssemblyNote]  (no BOM)

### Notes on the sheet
- Hardware, Logos, Assembly Notes

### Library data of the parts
!PCB1 = CMP-0003618-2: Manufacturer: Any; PartNumber: PROC191
FID1-FID6 = CMP-0077181-1: Fiducial mark.  There is nothing to buy or mount.
Logo1 = CMP-0074844-2: Manufacturer: Texas Instruments; SymbolCreator: a0412235; AEC Category: Q200; CompType: IC
Logo2 = CMP-0074838-1: Texas Instrument Corporate Signature; SymbolCreator: a0412235; Lib Reference: TI_Logo; Library Reference: Logo
Logo3 = CMP-0074847-1: FCC_disclaimer; Library Reference: Logo
Logo4 = CMP-0074769-4: Manufacturer: Texas Instruments; CompType: IC; AEC Category: Q200
ZZ2 = CMP-0077236-1
ZZ3 = CMP-0077237-1
ZZ4 = CMP-0077238-1

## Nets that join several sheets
GND: PROC191_Power (10 pins), PROC191_ExpansionConnector (53 pins), PROC191_TAS0 (58 pins), PROC191_TAS1 (58 pins)
PVDD: PROC191_Power (6 pins), PROC191_ExpansionConnector (TP6.1), PROC191_TAS0 (26 pins), PROC191_TAS1 (26 pins)
VDDIO: PROC191_Power (R52.2 R61.1 R64.1), PROC191_ExpansionConnector (20 pins), PROC191_TAS0 (6 pins), PROC191_TAS1 (6 pins)
VSYS5V0: PROC191_Power (R5.2 R56.2 R57.2), PROC191_ExpansionConnector (5 pins), PROC191_TAS0 (J25.2 R58.1 R63.1 R66.1), PROC191_TAS1 (J12.2 R37.1 R40.1 R42.1)
GPIO0: PROC191_ExpansionConnector (J1.42 TP20.1), PROC191_TAS0 (R86.2)
GPIO1: PROC191_ExpansionConnector (J1.44 TP22.1), PROC191_TAS1 (R41.2)
I2C_SCL: PROC191_ExpansionConnector (J1.18 J2.16 R7.1 U4.6), PROC191_TAS0 (U7.33), PROC191_TAS1 (U5.33)
I2C_SDA: PROC191_ExpansionConnector (J1.20 J2.18 R8.1 R19.1), PROC191_TAS0 (U7.34), PROC191_TAS1 (U5.34)
MCASPX_ACLKX0: PROC191_ExpansionConnector (R1.2), PROC191_TAS0 (R67.2 TP17.1 U7.27)
MCASPX_ACLKX1: PROC191_ExpansionConnector (R3.2), PROC191_TAS1 (R22.2 TP1.1 U5.27)
MCASPX_AR2: PROC191_ExpansionConnector (J1.28 J2.19), PROC191_TAS0 (R70.2 R78.1)
MCASPX_AR3: PROC191_ExpansionConnector (J1.30 J2.21), PROC191_TAS1 (R25.2 R33.1)
MCASPX_AX00: PROC191_ExpansionConnector (R14.2), PROC191_TAS0 (R69.2 TP19.1 U7.25)
MCASPX_AX01: PROC191_ExpansionConnector (R15.2), PROC191_TAS1 (R24.2 TP3.1 U5.25)
MCASPX_FSX0: PROC191_ExpansionConnector (R9.2), PROC191_TAS0 (R68.2 TP18.1 U7.26)
MCASPX_FSX1: PROC191_ExpansionConnector (R10.2), PROC191_TAS1 (R23.2 TP2.1 U5.26)
PORZ: PROC191_Power (R27.1), PROC191_ExpansionConnector (R4.2 R38.2 TP5.1 U8.4), PROC191_TAS0 (R95.2), PROC191_TAS1 (R83.2)
PORZ_SELECT: PROC191_Power (R53.2), PROC191_ExpansionConnector (R96.1 S1.2)

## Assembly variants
001: not fitted C32 C59 C64 R2 R7 R8 R17 R18 R28 R30 R52 R54 R55 R73 R75 R94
